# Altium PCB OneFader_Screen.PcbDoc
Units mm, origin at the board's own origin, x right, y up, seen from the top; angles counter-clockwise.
Board outline 62.1 x 43.6 mm, 2 copper layers (Top Layer, Bottom Layer); 12 components, 9 nets, 39 pads, 0 vias.
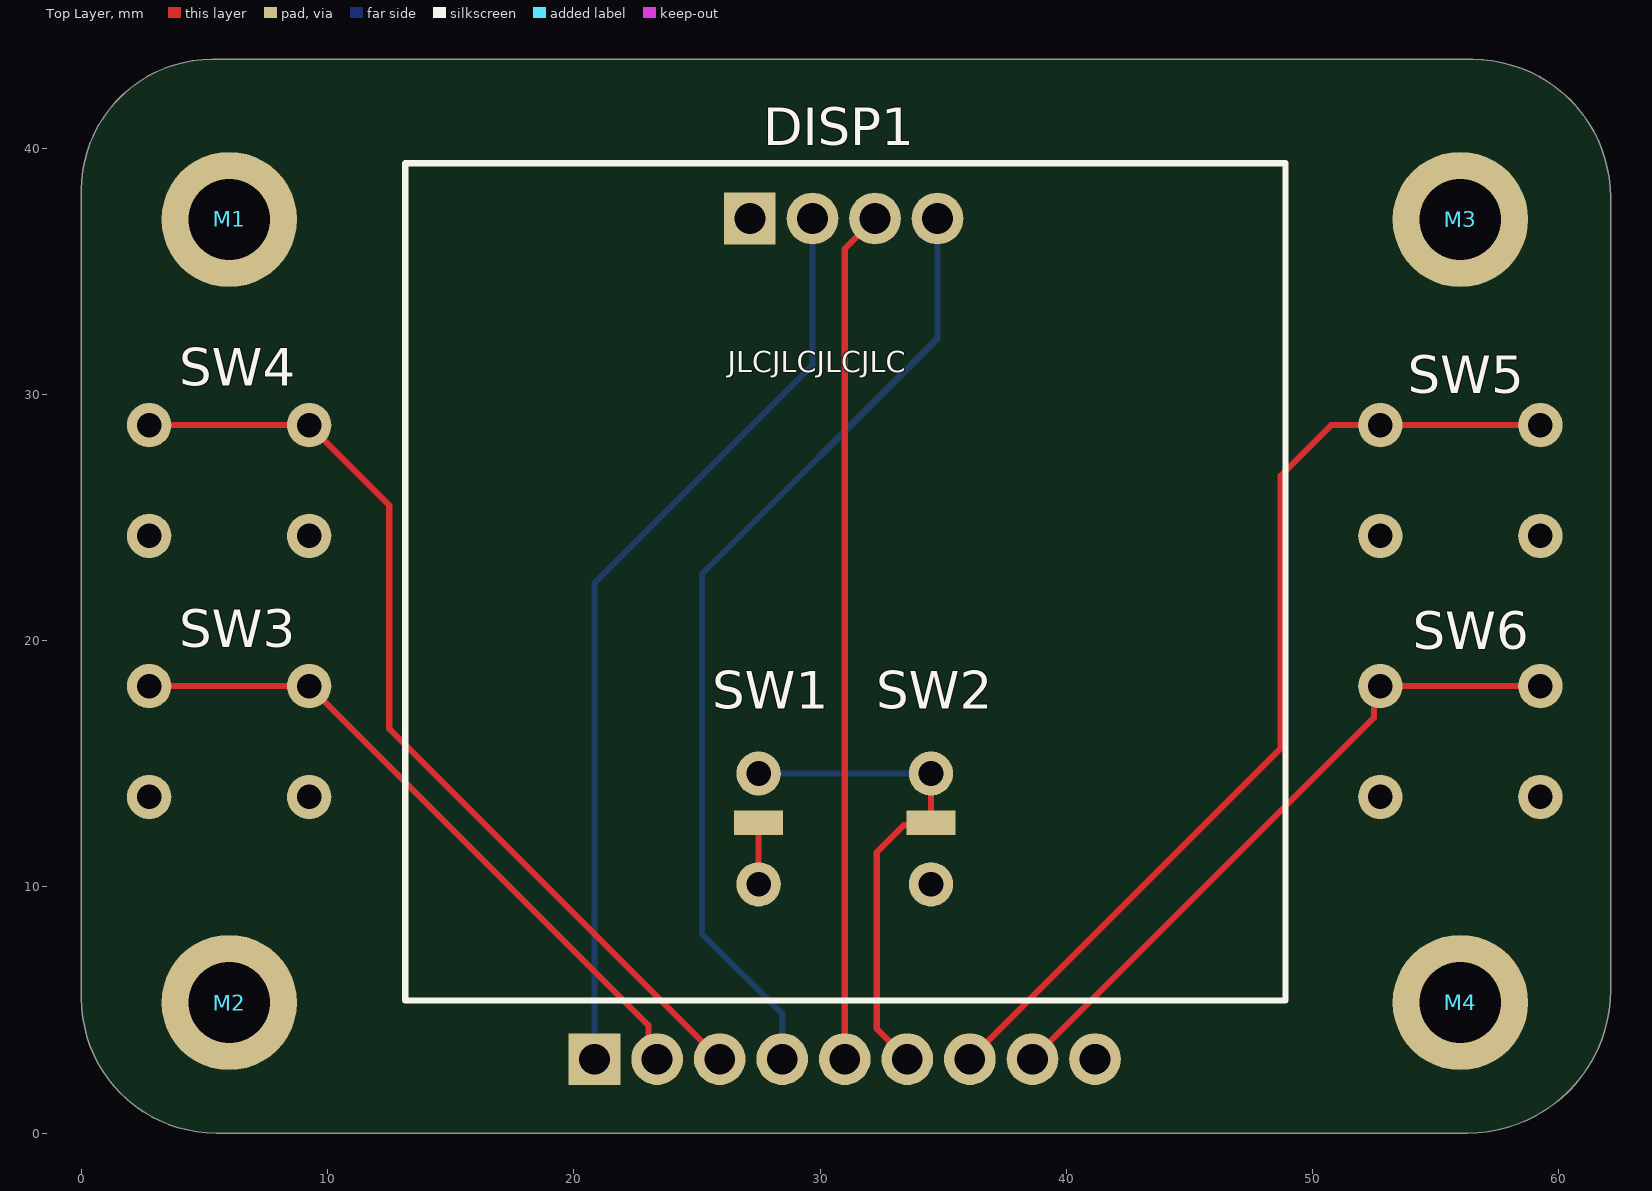
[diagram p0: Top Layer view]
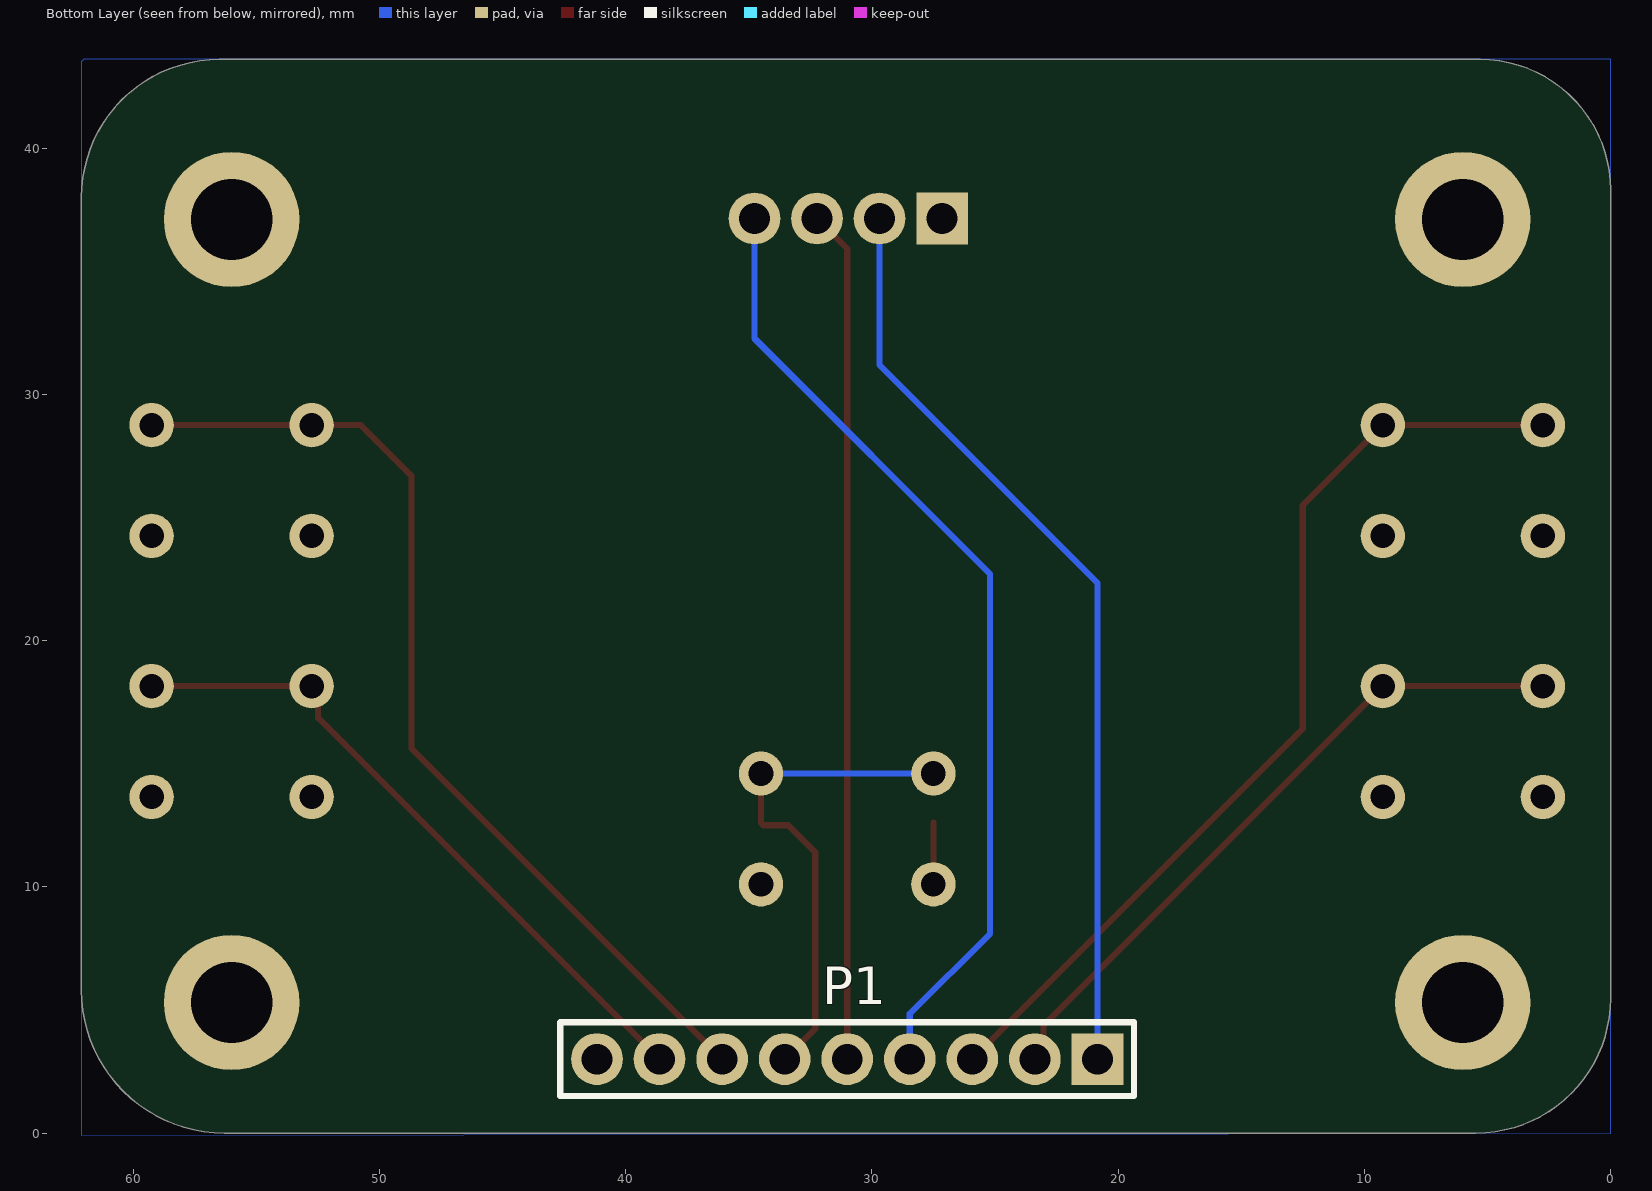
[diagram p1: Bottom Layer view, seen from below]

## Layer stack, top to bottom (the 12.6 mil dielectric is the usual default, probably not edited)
Top Solder: solder mask 0.0102, Solder Resist, Dk 3.5
Top Layer: signal copper 0.0356
Dielectric 1: dielectric 0.32, FR-4, Dk 4.8
Bottom Layer: signal copper 0.0356
Bottom Solder: solder mask 0.0102, Solder Resist, Dk 3.5

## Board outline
5.465,0 56.3,0 ccw(c56.3,5.8) 62.1,5.8 62.1,38 ccw(c56.5,38) 56.5,43.6 5.3,43.6 ccw(c5.3,38.3) 0,38.3 0,5.465 ccw(c5.465,5.465)

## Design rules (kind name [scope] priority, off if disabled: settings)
AssemblyTestPointUsage [All] p0: scope1count=1 scope1_0_kind=Board scope1_0_value=Board scope2count=1 scope2_0_kind=Board scope2_0_value=Board commentlength=0
AssemblyTestpoint [All] p0: scope1count=1 scope1_0_kind=Board scope1_0_value=Board scope2count=1 scope2_0_kind=Board scope2_0_value=Board commentlength=0
BoardOutlineClearance [All] p0: scope1count=1 scope1_0_kind=Board scope1_0_value=Board scope2count=1 scope2_0_kind=Board scope2_0_value=Board commentlength=0 gap=1
BoardOutlineClearance [All] p1: gap=1 ignorepadtopadclearanceinfootprint=FALSE
Clearance [All] p0: scope1count=1 scope1_0_kind=Board scope1_0_value=Board scope2count=1 scope2_0_kind=Board scope2_0_value=Board commentlength=0 gap=0.254
Clearance [All] p1: gap=0.254 ignorepadtopadclearanceinfootprint=FALSE except(0: Arc-Hole Track-Hole SMDPad-Hole THPad-Hole Via-Hole Fill-Hole Poly-Hole Region-Hole Text-Hole)
ComponentClearance [All] p0: scope1count=1 scope1_0_kind=Board scope1_0_value=Board scope2count=1 scope2_0_kind=Board scope2_0_value=Board commentlength=0 gap=0.254 collisioncheckmode=3
DiffPairsRouting [All] p0: scope1count=1 scope1_0_kind=Board scope1_0_value=Board scope2count=1 scope2_0_kind=Board scope2_0_value=Board commentlength=0
FabricationTestPointUsage [All] p0: scope1count=1 scope1_0_kind=Board scope1_0_value=Board scope2count=1 scope2_0_kind=Board scope2_0_value=Board commentlength=0 valid=0 allowmultiple=FALSE
FabricationTestpoint [All] p0: scope1count=1 scope1_0_kind=Board scope1_0_value=Board scope2count=1 scope2_0_kind=Board scope2_0_value=Board commentlength=0 side=3 testpointundercomponent=TRUE minsize=1.016 maxsize=2.54 preferedsize=1.524 minholesize=0 maxholesize=1.016 preferedholesize=0.813 testpointgrid=0.025
FanoutControl Fanout_BGA [All] p0 off: scope1count=1 scope1_0_kind=Board scope1_0_value=Board scope2count=1 scope2_0_kind=Board scope2_0_value=Board commentlength=69 // Protel DXP Scope 1 Expression Was: IsBGA   Fanout_BGA (Default Rule)
FanoutControl Fanout_LCC [All] p0 off: scope1count=1 scope1_0_kind=Board scope1_0_value=Board scope2count=1 scope2_0_kind=Board scope2_0_value=Board commentlength=69 // Protel DXP Scope 1 Expression Was: IsLCC   Fanout_LCC (Default Rule)
FanoutControl Fanout_SOIC [All] p0 off: scope1count=1 scope1_0_kind=Board scope1_0_value=Board scope2count=1 scope2_0_kind=Board scope2_0_value=Board commentlength=71 // Protel DXP Scope 1 Expression Was: IsSOIC   Fanout_SOIC (Default Rule)
FanoutControl Fanout_Small [All] p0 off: scope1count=1 scope1_0_kind=Board scope1_0_value=Board scope2count=1 scope2_0_kind=Board scope2_0_value=Board commentlength=84 // Protel DXP Scope 1 Expression Was: (CompPinCount < 5)   Fanout_Small (Default Rule)
FanoutControl Fanout_Default [All] p0: scope1count=1 scope1_0_kind=Board scope1_0_value=Board scope2count=1 scope2_0_kind=Board scope2_0_value=Board commentlength=30 // Fanout_Default (Default Rule)
Height [All] p0: scope1count=1 scope1_0_kind=Board scope1_0_value=Board scope2count=1 scope2_0_kind=Board scope2_0_value=Board commentlength=0
HoleSize [All] p0: scope1count=1 scope1_0_kind=Board scope1_0_value=Board scope2count=1 scope2_0_kind=Board scope2_0_value=Board commentlength=0 absolutevalues=TRUE maxlimit=5 minlimit=0.025 maxpercent=80.000 minpercent=20.000
HoleSize [All] p1: absolutevalues=TRUE maxlimit=5 minlimit=0.025 maxpercent=80.000 minpercent=20.000
HoleToHoleClearance [All] p0: scope1count=1 scope1_0_kind=Board scope1_0_value=Board scope2count=1 scope2_0_kind=Board scope2_0_value=Board commentlength=0
LayerPairs [All] p0: scope1count=1 scope1_0_kind=Board scope1_0_value=Board scope2count=1 scope2_0_kind=Board scope2_0_value=Board commentlength=0 enforce=TRUE
MinimumSolderMaskSliver [All] p0: scope1count=1 scope1_0_kind=Board scope1_0_value=Board scope2count=1 scope2_0_kind=Board scope2_0_value=Board commentlength=0
MinimumSolderMaskSliver [All] p1: minsoldermaskwidth=0.1
NetAntennae [All] p0: scope1count=1 scope1_0_kind=Board scope1_0_value=Board scope2count=1 scope2_0_kind=Board scope2_0_value=Board commentlength=0
PasteMaskExpansion [All] p0: scope1count=1 scope1_0_kind=Board scope1_0_value=Board scope2count=1 scope2_0_kind=Board scope2_0_value=Board commentlength=0 expansion=0
PlaneClearance [All] p0: scope1count=1 scope1_0_kind=Board scope1_0_value=Board scope2count=1 scope2_0_kind=Board scope2_0_value=Board commentlength=0 clearance=0.508
PlaneConnect [All] p0: scope1count=1 scope1_0_kind=Board scope1_0_value=Board scope2count=1 scope2_0_kind=Board scope2_0_value=Board commentlength=0 planeconnectstyle=Relief reliefexpansion=0.508 reliefentries=4 reliefconductorwidth=0.254 reliefairgap=0.254
PolygonConnect [All] p0: scope1count=1 scope1_0_kind=Board scope1_0_value=Board scope2count=1 scope2_0_kind=Board scope2_0_value=Board commentlength=0 connectstyle=Relief reliefconductorwidth=0.254 reliefentries=4 polygonreliefangle="90 Angle"
PolygonConnect [All] p1: connectstyle=Relief reliefconductorwidth=0.254 reliefentries=4 polygonreliefangle="90 Angle" airgapwidth=0.254
RoutingCorners [All] p0: scope1count=1 scope1_0_kind=Board scope1_0_value=Board scope2count=1 scope2_0_kind=Board scope2_0_value=Board commentlength=0 cornerstyle=45-Degree minsetback=2.54 maxsetback=2.54
RoutingLayers [All] p0: scope1count=1 scope1_0_kind=Board scope1_0_value=Board scope2count=1 scope2_0_kind=Board scope2_0_value=Board commentlength=0 top layer=Automatic bottom layer=Automatic
RoutingPriority [All] p0: scope1count=1 scope1_0_kind=Board scope1_0_value=Board scope2count=1 scope2_0_kind=Board scope2_0_value=Board commentlength=0
RoutingTopology [All] p0: scope1count=1 scope1_0_kind=Board scope1_0_value=Board scope2count=1 scope2_0_kind=Board scope2_0_value=Board commentlength=0 topology=Shortest
RoutingVias [All] p0: scope1count=1 scope1_0_kind=Board scope1_0_value=Board scope2count=1 scope2_0_kind=Board scope2_0_value=Board commentlength=0 holewidth=0.711 width=1.27 viastyle="Through Hole" minholewidth=0.711 minwidth=1.27 maxholewidth=0.711 maxwidth=1.27
RoutingVias [All] p1: holewidth=0.711 width=1.27 viastyle="Through Hole" minholewidth=0.711 minwidth=1.27 maxholewidth=0.711 maxwidth=1.27
ShortCircuit [All] p0: scope1count=1 scope1_0_kind=Board scope1_0_value=Board scope2count=1 scope2_0_kind=Board scope2_0_value=Board commentlength=0 allowed=FALSE
SilkToBoardRegionClearance [All] p0: scope1count=1 scope1_0_kind=Board scope1_0_value=Board scope2count=1 scope2_0_kind=Board scope2_0_value=Board commentlength=0
SilkToSilkClearance [All] p0: scope1count=1 scope1_0_kind=Board scope1_0_value=Board scope2count=1 scope2_0_kind=Board scope2_0_value=Board commentlength=0
SilkToSolderMaskClearance [All] p0 off: scope1count=1 scope1_0_kind=Board scope1_0_value=Board scope2count=1 scope2_0_kind=Board scope2_0_value=Board commentlength=44 // Protel DXP Scope 1 Expression Was: IsPad
SolderMaskExpansion [All] p0: scope1count=1 scope1_0_kind=Board scope1_0_value=Board scope2count=1 scope2_0_kind=Board scope2_0_value=Board commentlength=0 expansion=0.102
SolderMaskExpansion [All] p1: expansion=0.102 istentingtop=FALSE
UnRoutedNet [All] p0: scope1count=1 scope1_0_kind=Board scope1_0_value=Board scope2count=1 scope2_0_kind=Board scope2_0_value=Board commentlength=0
UnpouredPolygon [All] p0: scope1count=1 scope1_0_kind=Board scope1_0_value=Board scope2count=1 scope2_0_kind=Board scope2_0_value=Board commentlength=0
Width [All] p0: scope1count=1 scope1_0_kind=Board scope1_0_value=Board scope2count=1 scope2_0_kind=Board scope2_0_value=Board commentlength=0 maxlimit=0.254 minlimit=0.254 preferedwidth=0.254
Width [All] p1: maxlimit=0.254 minlimit=0.254 preferedwidth=0.254
28 further rules are at their usual default settings.

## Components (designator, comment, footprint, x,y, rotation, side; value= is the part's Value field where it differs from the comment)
DISP1 "SSD1306" SSD1306_1.3 31,21.7 r0 top
M1 "M3 Flat Screw" "M3 Screw"#1 6,37.1 r0 top
M2 "M3 Flat Screw" "M3 Screw"#1 6,5.3 r0 top
M3 "M3 Flat Screw" "M3 Screw"#2 56,36.8 r0 top
M4 "M3 Flat Screw" "M3 Screw"#1 56,5.3 r0 top
P1 "9 Header" "9 Header" 31,3 r270 bottom
SW1 "Momentary Button" TD-19XA 31,12.6 r180 top
SW2 "Momentary Button" TS1127 31,12.6 r0 top
SW3 "Momentary Button" "Tactile Button 6*6*5mm" 6,15.9 r0 top
SW4 "Momentary Button" "Tactile Button 6*6*5mm" 6,26.5 r0 top
SW5 "Momentary Button" "Tactile Button 6*6*5mm" 56,26.5 r0 top
SW6 "Momentary Button" "Tactile Button 6*6*5mm" 56,15.9 r0 top

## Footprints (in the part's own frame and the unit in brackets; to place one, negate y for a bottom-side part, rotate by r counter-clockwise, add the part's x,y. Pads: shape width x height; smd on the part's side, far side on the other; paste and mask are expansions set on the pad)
"9 Header" [mm]
  rect 2.1x2.1 hole 1.25: 1(0,10.16)
  round 2.1 hole 1.25: 2(0,7.62) 3(0,5.08) 4(0,2.54) 5(0,0) 6(0,-2.54) 7(0,-5.08) 8(0,-7.62) 9(0,-10.16)
  silkscreen extent -1.5,-11.65 1.5,11.65
"M3 Screw"#1 [mm]
  round 5.5 hole 3.3: 1(0,0)
"M3 Screw"#2 [mm]
  round 5.5 hole 3.3: 1(0,0.3)
SSD1306_1.3 [mm]
  rect 2.1x2.1 hole 1.25: 1(-3.853,15.436)
  round 2.1 hole 1.25: 2(-1.313,15.436) 3(1.227,15.436) 4(3.767,15.436)
  silkscreen extent -17.85,-16.31 17.9,17.69
"Tactile Button 6*6*5mm" [mm]
  round 1.8 hole 1: 1(-3.25,2.25) 1(3.25,2.25) 2(-3.25,-2.25) 2(3.25,-2.25)
TD-19XA [mm] "TACT SWITCH 6.1*3.7*2.5MM SMD SPST-NO"
  rect 2x1 smd: 1(-3.5,0) 2(3.5,0)
TS1127 [mm] "TACT SWITCH 6.2*2.5 THROUGH HOLE SPST-NO RED BUTTON"
  round 1.8 hole 1: 1(-3.5,2) 1(3.5,2) 2(-3.5,-2.5) 2(3.5,-2.5)

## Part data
DISP1: library part SSD1306_1.3, "SSD1306 128*64 1.3Inch I2C OLED Module"

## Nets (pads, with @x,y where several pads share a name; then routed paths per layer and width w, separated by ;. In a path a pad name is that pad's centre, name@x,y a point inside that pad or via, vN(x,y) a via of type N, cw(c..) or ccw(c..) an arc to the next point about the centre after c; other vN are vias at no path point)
3V3: DISP1.2 P1.1 | length 37.8
  Bottom Layer w0.254: P1.1 20.84,22.34 29.687,31.187 DISP1.2
BUTTON_1: P1.6 SW1.1 SW2.1 | length 20.6
  Top Layer w0.254: P1.6 32.3,4.24 32.3,11.4 33.4,12.5 34.4,12.5 SW1.1 SW2.1@34.5,14.6
  Bottom Layer w0.254: SW2.1@27.5,14.6 SW2.1@34.5,14.6
BUTTON_2: P1.2 SW3.1 | length 27.5
  Top Layer w0.254: SW3.1@2.75,18.15 9.25,18.15 23.027,4.373 23.027,3.353 P1.2
BUTTON_3: P1.3 SW4.1 | length 39.2
  Top Layer w0.254: SW4.1@2.75,28.75 9.25,28.75 12.5,25.5 12.5,16.42 P1.3
BUTTON_4: P1.7 SW5.1 | length 40.3
  Top Layer w0.254: P1.7 48.7,15.62 48.7,26.7 50.75,28.75 52.75,28.75 SW5.1@59.25,28.75
BUTTON_5: P1.8 SW6.1 | length 27.5
  Top Layer w0.254: P1.8 52.489,16.869 52.489,17.889 52.75,18.15 SW6.1@59.25,18.15
GND: DISP1.1 M1.1 M2.1 M3.1 M4.1 P1.9 SW1.2 SW2.2 SW3.2 SW4.2 SW5.2 SW6.2 | length 2.5
  Top Layer w0.254: SW2.2@27.5,10.1 SW1.2
SCL: DISP1.3 P1.5 | length 34.6
  Top Layer w0.254: P1.5 31,35.909 DISP1.3
SDA: DISP1.4 P1.4 | length 39.4
  Bottom Layer w0.254: P1.4 28.46,4.84 25.2,8.1 25.2,22.7 34.767,32.267 DISP1.4

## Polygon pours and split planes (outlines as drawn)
GND on Bottom Layer "NONET_L-01_P-001" (solid, pour order 0): 0,0 0,43.6 62,43.6 62.1,43.5 62.1,-0.1

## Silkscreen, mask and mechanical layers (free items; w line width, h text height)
Top Overlay:
  text "JLCJLCJLCJLC" at 26.243,30.9 h0.85
Board Outline:
  lines w0.254: 0,5.5 ccw(c5.5,5.5) 5.5,0 56.5,0 ccw(c56.5,5.5) 62,5.5 62,38.1 ccw(c56.5,38.1) 56.5,43.6 5.5,43.6 ccw(c5.5,38.1) 0,38.1 0,5.5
